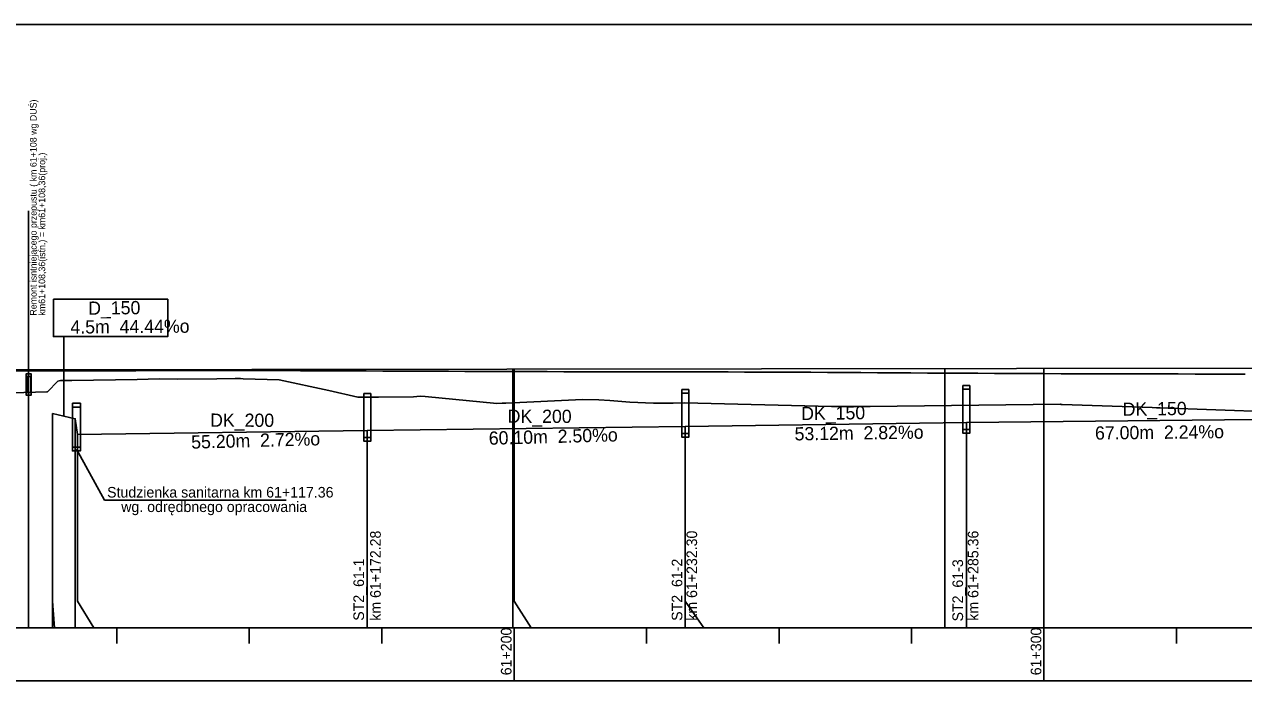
# Model space of a CAD drawing. Extents: x 6445630 to 6518227, y 5499240 to 5511716.
# Drawn here: x 6460338.8 to 6460568.9, y 5508580.5 to 5508705.3 of the extents above; entities that cross this region are included whole.
import ezdxf

# ---------------------------------------------------------------- set-up
doc = ezdxf.new("R2010")
doc.units = 0
for name, color, linetype in [('TOR_PROF-drenaze', 7, 'Continuous'), ('TOR_PROF-drenokolektory', 7, 'Continuous'), ('TOR_PROF-obiekty+opisy', 7, 'Continuous'), ('TOR_PROF-opisy glowne', 7, 'Continuous'), ('TOR_PROF-opisy pomocnicze', 7, 'Continuous'), ('TOR_PROF-rowy otwarte', 7, 'Continuous'), ('TOR_PROF-studnie i osadniki', 7, 'Continuous'), ('TOR_PROF-tabelka-pochylenia proj T1', 7, 'Continuous'), ('TOR_PROF-tor istniejacy T2', 7, 'Continuous'), ('TOR_PROF-tor projektowany', 7, 'Continuous'), ('TOR_PROF-uklad odniesienia', 7, 'Continuous'), ('TOR_RAMKI-dodatkowe3', 7, 'Continuous'), ('TOR_RAMKI-MASKA WYCIECIA', 7, 'Continuous')]:
    doc.layers.add(name, color=color, linetype=linetype)

msp = doc.modelspace()

# ---------------------------------------------------------------- linework, layer by layer
at = {"layer": 'TOR_PROF-drenaze'}
for points in [[(6460463.51, 5508629.29), (6460516.57, 5508630.04)], [(6460516.57, 5508630.04), (6460583.51, 5508630.79)]]:
    msp.add_lwpolyline(points, dxfattribs=at)
at = {"layer": 'TOR_PROF-drenokolektory'}
for points in [[(6460344.08, 5508631.79), (6460348.35, 5508630.79), (6460348.81, 5508627.79), (6460403.49, 5508628.54)], [(6460344.08, 5508631.79), (6460344.08, 5508596.29), (6460344.47, 5508591.29), (6460344.47, 5508591.29)], [(6460344.08, 5508631.79), (6460344.08, 5508596.29), (6460344.47, 5508591.29), (6460344.47, 5508591.29)], [(6460344.08, 5508631.79), (6460344.08, 5508596.29), (6460344.08, 5508591.29), (6460344.08, 5508591.29)], [(6460348.35, 5508630.79), (6460348.35, 5508596.29), (6460348.35, 5508591.29), (6460348.35, 5508591.29)], [(6460403.49, 5508628.54), (6460463.51, 5508629.29)], [(6460463.51, 5508629.29), (6460463.51, 5508596.29), (6460463.51, 5508591.29), (6460463.51, 5508591.29)], [(6460463.51, 5508629.29), (6460463.51, 5508596.29), (6460463.51, 5508591.29), (6460463.51, 5508591.29)], [(6460463.51, 5508629.29), (6460463.51, 5508596.29), (6460463.51, 5508591.29), (6460463.51, 5508591.29)], [(6460463.51, 5508629.29), (6460463.51, 5508596.29), (6460463.51, 5508591.29), (6460463.51, 5508591.29)], [(6460463.51, 5508629.29), (6460463.51, 5508596.29), (6460463.51, 5508591.29), (6460463.51, 5508591.29)], [(6460463.51, 5508629.29), (6460463.51, 5508596.29), (6460467.01, 5508591.29), (6460467.01, 5508591.29)], [(6460516.57, 5508630.04), (6460516.57, 5508596.29), (6460516.57, 5508591.29), (6460516.57, 5508591.29)], [(6460516.57, 5508630.04), (6460516.57, 5508596.29), (6460516.57, 5508591.29), (6460516.57, 5508591.29)], [(6460516.57, 5508630.04), (6460516.57, 5508596.29), (6460516.57, 5508591.29), (6460516.57, 5508591.29)], [(6460516.57, 5508630.04), (6460516.57, 5508596.29), (6460516.57, 5508591.29), (6460516.57, 5508591.29)], [(6460516.57, 5508630.04), (6460516.57, 5508596.29), (6460516.57, 5508591.29), (6460516.57, 5508591.29)], [(6460348.81, 5508627.79), (6460348.81, 5508596.29), (6460351.85, 5508591.29), (6460351.85, 5508591.29)], [(6460403.49, 5508628.54), (6460403.49, 5508596.29), (6460403.49, 5508591.29), (6460403.49, 5508591.29)], [(6460403.49, 5508628.54), (6460403.49, 5508596.29), (6460403.49, 5508591.29), (6460403.49, 5508591.29)], [(6460403.49, 5508628.54), (6460403.49, 5508596.29), (6460403.49, 5508591.29), (6460403.49, 5508591.29)], [(6460403.49, 5508628.54), (6460403.49, 5508596.29), (6460403.49, 5508591.29), (6460403.49, 5508591.29)], [(6460403.49, 5508628.54), (6460403.49, 5508596.29), (6460403.49, 5508591.29), (6460403.49, 5508591.29)]]:
    msp.add_lwpolyline(points, dxfattribs=at)
at = {"layer": 'TOR_PROF-obiekty+opisy'}
for p, q in [((6460339.57, 5508591.29), (6460339.57, 5508670.03)), ((6460348.59, 5508625.06), (6460353.88, 5508615.37)), ((6460353.88, 5508615.37), (6460388.18, 5508615.37))]:
    msp.add_line(p, q, dxfattribs=at)
for points in [[(6460340.03, 5508639.29), (6460339.11, 5508639.29), (6460339.11, 5508635.21), (6460340.03, 5508635.21)], [(6460339.95, 5508638.75), (6460339.2, 5508638.75), (6460339.2, 5508635.75), (6460339.95, 5508635.75)]]:
    msp.add_lwpolyline(points, close=True, dxfattribs=at)
for points in [[(6460340.03, 5508635.21), (6460340.03, 5508639.29), (6460339.11, 5508639.29), (6460339.11, 5508635.21), (6460340.03, 5508635.21)], [(6460339.95, 5508635.75), (6460339.2, 5508635.75), (6460339.2, 5508638.75), (6460339.95, 5508638.75), (6460339.95, 5508635.75)]]:
    msp.add_lwpolyline(points, dxfattribs=at)
at = {"layer": 'TOR_PROF-opisy glowne'}
msp.add_line((6460346.22, 5508631.29), (6460346.22, 5508646.29), dxfattribs=at)
msp.add_lwpolyline([(6460344.25, 5508653.35), (6460365.81, 5508653.35), (6460365.81, 5508646.29), (6460344.25, 5508646.29)], close=True, dxfattribs=at)
at = {"layer": 'TOR_PROF-rowy otwarte'}
for points in [[(6460344.08, 5508631.79), (6460344.08, 5508596.29), (6460344.08, 5508591.29), (6460344.08, 5508591.29)], [(6460348.35, 5508630.79), (6460348.35, 5508596.29), (6460348.35, 5508591.29), (6460348.35, 5508591.29)], [(6460463.51, 5508629.29), (6460463.51, 5508596.29), (6460463.51, 5508591.29), (6460463.51, 5508591.29)], [(6460463.51, 5508629.29), (6460463.51, 5508596.29), (6460467.01, 5508591.29), (6460467.01, 5508591.29)], [(6460516.57, 5508630.04), (6460516.57, 5508596.29), (6460516.57, 5508591.29), (6460516.57, 5508591.29)], [(6460348.81, 5508627.79), (6460348.81, 5508596.29), (6460351.85, 5508591.29), (6460351.85, 5508591.29)], [(6460403.49, 5508628.54), (6460403.49, 5508596.29), (6460403.49, 5508591.29), (6460403.49, 5508591.29)]]:
    msp.add_lwpolyline(points, dxfattribs=at)
at = {"layer": 'TOR_PROF-studnie i osadniki'}
for p, q in [((6460462.86, 5508636.29), (6460462.86, 5508627.29)), ((6460462.86, 5508636.29), (6460464.16, 5508636.29)), ((6460464.16, 5508636.29), (6460464.16, 5508627.29)), ((6460515.92, 5508637.04), (6460515.92, 5508628.04)), ((6460515.92, 5508637.04), (6460517.22, 5508637.04)), ((6460517.22, 5508637.04), (6460517.22, 5508628.04)), ((6460402.84, 5508635.54), (6460402.84, 5508626.54)), ((6460402.84, 5508635.54), (6460404.14, 5508635.54)), ((6460404.14, 5508635.54), (6460404.14, 5508626.54)), ((6460347.83, 5508633.69), (6460347.83, 5508624.69)), ((6460347.93, 5508633.69), (6460349.23, 5508633.69)), ((6460349.33, 5508633.69), (6460349.33, 5508624.69)), ((6460462.86, 5508627.29), (6460464.16, 5508627.29)), ((6460515.92, 5508628.04), (6460517.22, 5508628.04)), ((6460347.83, 5508624.69), (6460349.33, 5508624.69)), ((6460402.84, 5508626.54), (6460404.14, 5508626.54))]:
    msp.add_line(p, q, dxfattribs=at)
for points in [[(6460462.86, 5508636.29), (6460464.16, 5508636.29), (6460464.16, 5508635.59), (6460462.86, 5508635.59)], [(6460515.92, 5508637.04), (6460517.22, 5508637.04), (6460517.22, 5508636.34), (6460515.92, 5508636.34)], [(6460402.84, 5508635.54), (6460404.14, 5508635.54), (6460404.14, 5508634.84), (6460402.84, 5508634.84)], [(6460347.83, 5508633.69), (6460349.33, 5508633.69), (6460349.33, 5508632.99), (6460347.83, 5508632.99)], [(6460402.84, 5508627.24), (6460404.14, 5508627.24), (6460404.14, 5508626.54), (6460402.84, 5508626.54)], [(6460462.86, 5508627.99), (6460464.16, 5508627.99), (6460464.16, 5508627.29), (6460462.86, 5508627.29)], [(6460515.92, 5508628.74), (6460517.22, 5508628.74), (6460517.22, 5508628.04), (6460515.92, 5508628.04)], [(6460347.83, 5508625.39), (6460349.33, 5508625.39), (6460349.33, 5508624.69), (6460347.83, 5508624.69)]]:
    msp.add_lwpolyline(points, close=True, dxfattribs=at)
at = {"layer": 'TOR_PROF-tabelka-pochylenia proj T1'}
msp.add_lwpolyline([(6452331.21, 5508571.29), (6462731.21, 5508571.29), (6462731.21, 5508581.29), (6452331.21, 5508581.29)], close=True, dxfattribs=at)
at = {"layer": 'TOR_PROF-tor istniejacy T2'}
msp.add_lwpolyline([(6460569.19, 5508639.23), (6460566.04, 5508639.23), (6460562.88, 5508639.23), (6460559.73, 5508639.23), (6460556.57, 5508639.24), (6460553.42, 5508639.24), (6460550.26, 5508639.25), (6460547.11, 5508639.25), (6460543.95, 5508639.26), (6460540.8, 5508639.27), (6460537.65, 5508639.28), (6460534.49, 5508639.29), (6460531.34, 5508639.3), (6460528.18, 5508639.31), (6460525.03, 5508639.33), (6460521.87, 5508639.34), (6460518.72, 5508639.36), (6460515.56, 5508639.37), (6460512.41, 5508639.39), (6460509.26, 5508639.41), (6460506.1, 5508639.43), (6460502.95, 5508639.45), (6460499.79, 5508639.47), (6460496.64, 5508639.49), (6460493.49, 5508639.51), (6460490.33, 5508639.54), (6460487.18, 5508639.56), (6460484.03, 5508639.59), (6460480.92, 5508639.59), (6460477.82, 5508639.6), (6460474.71, 5508639.6), (6460471.61, 5508639.61), (6460468.51, 5508639.61), (6460465.4, 5508639.62), (6460462.3, 5508639.62), (6460459.19, 5508639.63), (6460456.09, 5508639.63), (6460452.98, 5508639.64), (6460449.88, 5508639.65), (6460446.77, 5508639.66), (6460443.67, 5508639.66), (6460440.56, 5508639.67), (6460437.46, 5508639.68), (6460434.35, 5508639.69), (6460431.24, 5508639.7), (6460428.14, 5508639.71), (6460425.03, 5508639.72), (6460421.93, 5508639.73), (6460418.82, 5508639.74), (6460415.72, 5508639.75), (6460412.61, 5508639.77), (6460409.5, 5508639.78), (6460406.4, 5508639.79), (6460403.29, 5508639.8), (6460400.18, 5508639.82), (6460397.08, 5508639.83), (6460393.97, 5508639.85), (6460390.87, 5508639.86), (6460387.76, 5508639.87), (6460384.65, 5508639.89), (6460335, 5508639.74)], dxfattribs=at)
at = {"layer": 'TOR_PROF-tor projektowany'}
msp.add_line((6459231.21, 5508638.54), (6460751.21, 5508640.59), dxfattribs=at)
msp.add_line((6459231.21, 5508638.54), (6460751.21, 5508640.59), dxfattribs=at)
for points in [[(6460430.94, 5508640.16), (6460430.94, 5508596.29), (6460430.94, 5508591.29), (6460430.94, 5508591.29)], [(6460430.94, 5508640.16), (6460430.94, 5508596.29), (6460430.94, 5508591.29), (6460430.94, 5508591.29)], [(6460431.21, 5508640.16), (6460431.21, 5508596.29), (6460434.44, 5508591.29), (6460434.44, 5508591.29)], [(6460431.21, 5508640.16), (6460431.21, 5508596.29), (6460434.44, 5508591.29), (6460434.44, 5508591.29)], [(6460512.51, 5508640.27), (6460512.51, 5508596.29), (6460512.51, 5508591.29), (6460512.51, 5508591.29)], [(6460512.51, 5508640.27), (6460512.51, 5508596.29), (6460512.51, 5508591.29), (6460512.51, 5508591.29)], [(6460531.21, 5508640.29), (6460531.21, 5508596.29), (6460531.21, 5508591.29), (6460531.21, 5508591.29)], [(6460531.21, 5508640.29), (6460531.21, 5508596.29), (6460531.21, 5508591.29), (6460531.21, 5508591.29)]]:
    msp.add_lwpolyline(points, dxfattribs=at)
at = {"layer": 'TOR_PROF-uklad odniesienia'}
for p, q in [((6452331.21, 5508591.29), (6462731.21, 5508591.29)), ((6452331.21, 5508591.29), (6462731.21, 5508591.29)), ((6460356.21, 5508588.29), (6460356.21, 5508591.29)), ((6460356.21, 5508588.29), (6460356.21, 5508591.29)), ((6460381.21, 5508588.29), (6460381.21, 5508591.29)), ((6460381.21, 5508588.29), (6460381.21, 5508591.29)), ((6460406.21, 5508588.29), (6460406.21, 5508591.29)), ((6460406.21, 5508588.29), (6460406.21, 5508591.29)), ((6460431.21, 5508581.29), (6460431.21, 5508591.29)), ((6460431.21, 5508581.29), (6460431.21, 5508591.29)), ((6460456.21, 5508588.29), (6460456.21, 5508591.29)), ((6460456.21, 5508588.29), (6460456.21, 5508591.29)), ((6460481.21, 5508588.29), (6460481.21, 5508591.29)), ((6460481.21, 5508588.29), (6460481.21, 5508591.29)), ((6460506.21, 5508588.29), (6460506.21, 5508591.29)), ((6460506.21, 5508588.29), (6460506.21, 5508591.29)), ((6460531.21, 5508581.29), (6460531.21, 5508591.29)), ((6460531.21, 5508581.29), (6460531.21, 5508591.29)), ((6460556.21, 5508588.29), (6460556.21, 5508591.29)), ((6460556.21, 5508588.29), (6460556.21, 5508591.29))]:
    msp.add_line(p, q, dxfattribs=at)
at = {"layer": 'TOR_RAMKI-dodatkowe3'}
for p, q in [((6460343.13, 5508635.86), (6460345.05, 5508637.87)), ((6460345.05, 5508637.87), (6460345.55, 5508638.01)), ((6460345.55, 5508638.01), (6460347.75, 5508638.03)), ((6460347.75, 5508638.03), (6460360.02, 5508638.19)), ((6460360.02, 5508638.19), (6460364.22, 5508638.29)), ((6460364.22, 5508638.29), (6460367.63, 5508638.24)), ((6460367.63, 5508638.24), (6460375.08, 5508638.32)), ((6460375.08, 5508638.32), (6460378.57, 5508638.36)), ((6460378.57, 5508638.36), (6460379.54, 5508638.35)), ((6460379.54, 5508638.35), (6460380.03, 5508638.32)), ((6460380.03, 5508638.32), (6460386.84, 5508638.13)), ((6460386.84, 5508638.13), (6460396.26, 5508636.11)), ((6460336.51, 5508635.67), (6460343.03, 5508635.84)), ((6460343.03, 5508635.84), (6460343.1, 5508635.85)), ((6460343.1, 5508635.85), (6460343.13, 5508635.86)), ((6460396.26, 5508636.11), (6460401.71, 5508634.88)), ((6460401.71, 5508634.88), (6460405.62, 5508634.88)), ((6460405.62, 5508634.88), (6460412.2, 5508634.93)), ((6460412.2, 5508634.93), (6460413.5, 5508635.04)), ((6460413.5, 5508635.04), (6460414.41, 5508634.97)), ((6460414.41, 5508634.97), (6460427.91, 5508633.67)), ((6460429.63, 5508633.73), (6460444.14, 5508634.44)), ((6460444.14, 5508634.44), (6460447.22, 5508634.37)), ((6460447.22, 5508634.37), (6460449.25, 5508634.24)), ((6460449.25, 5508634.24), (6460453.07, 5508633.92)), ((6460453.07, 5508633.92), (6460457.5, 5508633.71)), ((6460427.91, 5508633.67), (6460428.97, 5508633.71)), ((6460428.97, 5508633.71), (6460429.63, 5508633.73)), ((6460457.5, 5508633.71), (6460461.22, 5508633.7)), ((6460461.22, 5508633.7), (6460463.34, 5508633.79)), ((6460463.34, 5508633.79), (6460491.1, 5508633.07)), ((6460491.1, 5508633.07), (6460491.56, 5508633.09)), ((6460491.56, 5508633.09), (6460492.28, 5508633.07)), ((6460492.28, 5508633.07), (6460496.15, 5508633.09)), ((6460496.15, 5508633.09), (6460496.26, 5508633.1)), ((6460496.26, 5508633.1), (6460498.41, 5508633.11)), ((6460498.41, 5508633.11), (6460534.28, 5508633.5)), ((6460534.28, 5508633.5), (6460534.46, 5508633.47)), ((6460534.46, 5508633.47), (6460534.67, 5508633.49)), ((6460534.67, 5508633.49), (6460551.61, 5508632.89)), ((6460551.61, 5508632.89), (6460551.61, 5508632.89)), ((6460551.61, 5508632.89), (6460552.46, 5508632.86)), ((6460552.47, 5508632.86), (6460553.01, 5508632.86)), ((6460553.01, 5508632.86), (6460553.16, 5508632.86)), ((6460553.16, 5508632.86), (6460583.92, 5508631.73))]:
    msp.add_line(p, q, dxfattribs=at)
at = {"layer": 'TOR_RAMKI-MASKA WYCIECIA'}
msp.add_lwpolyline([(6459211.14, 5508418.29), (6460761.14, 5508418.29), (6460761.14, 5508705.29), (6459211.14, 5508705.29)], close=True, dxfattribs=at)

# ---------------------------------------------------------------- texts
at = {"layer": 'TOR_PROF-drenaze'}
for s, rotation, p in [('D_150', 0.657, (6460350.82, 5508650.42)), ('4.5m  44.44%o  ', 0.4353, (6460347.46, 5508646.86)), ('DK_150 ', 0.8099, (6460546.08, 5508631.32)), ('DK_200', 359.8417, (6460373.82, 5508629.27)), ('DK_200', 359.8417, (6460429.98, 5508630.01)), ('DK_150 ', 0.8099, (6460485.4, 5508630.52)), ('53.12m  2.82%o  ', 0.8099, (6460484.16, 5508626.67)), ('67.00m  2.24%o  ', 0.6419, (6460540.86, 5508626.83)), ('55.20m  2.72%o  ', 1.5506, (6460370.28, 5508625.11)), ('60.10m  2.50%o  ', 1.5506, (6460426.45, 5508625.85))]:
    msp.add_text(s, height=2.5, rotation=rotation, dxfattribs=at).set_placement(p)
at = {"layer": 'TOR_PROF-obiekty+opisy'}
for s, p in [('Remont isntniejącego przepustu ( km 61+108 wg DUŚ)', (6460341.07, 5508650.26)), ('km61+108,36(istn.) = km61+108,36(proj.) ', (6460342.69, 5508650.26))]:
    msp.add_text(s, height=1.25, rotation=90, dxfattribs=at).set_placement(p)
at = {"layer": 'TOR_PROF-opisy glowne'}
for s, p in [('km 61+172.28', (6460406.03, 5508592.61)), ('km 61+232.30', (6460465.74, 5508592.61)), ('km 61+285.36', (6460518.84, 5508592.61)), ('ST2_61-1', (6460402.87, 5508592.61)), ('ST2_61-2', (6460462.95, 5508592.59)), ('ST2_61-3', (6460515.94, 5508592.48))]:
    msp.add_text(s, height=2, rotation=90, dxfattribs=at).set_placement(p)
at = {"layer": 'TOR_PROF-opisy pomocnicze'}
for s, p in [('Studzienka sanitarna km 61+117.36', (6460354.37, 5508615.89)), ('wg. odrędbnego opracowania', (6460357.04, 5508613.15))]:
    msp.add_text(s, height=2, dxfattribs=at).set_placement(p)
at = {"layer": 'TOR_PROF-uklad odniesienia'}
for s, p in [('61+200', (6460430.71, 5508582.31)), ('61+200', (6460430.71, 5508582.31)), ('61+300', (6460530.71, 5508582.31)), ('61+300', (6460530.71, 5508582.31))]:
    msp.add_text(s, height=2, rotation=90, dxfattribs=at).set_placement(p)

doc.saveas('drawing.dxf')
